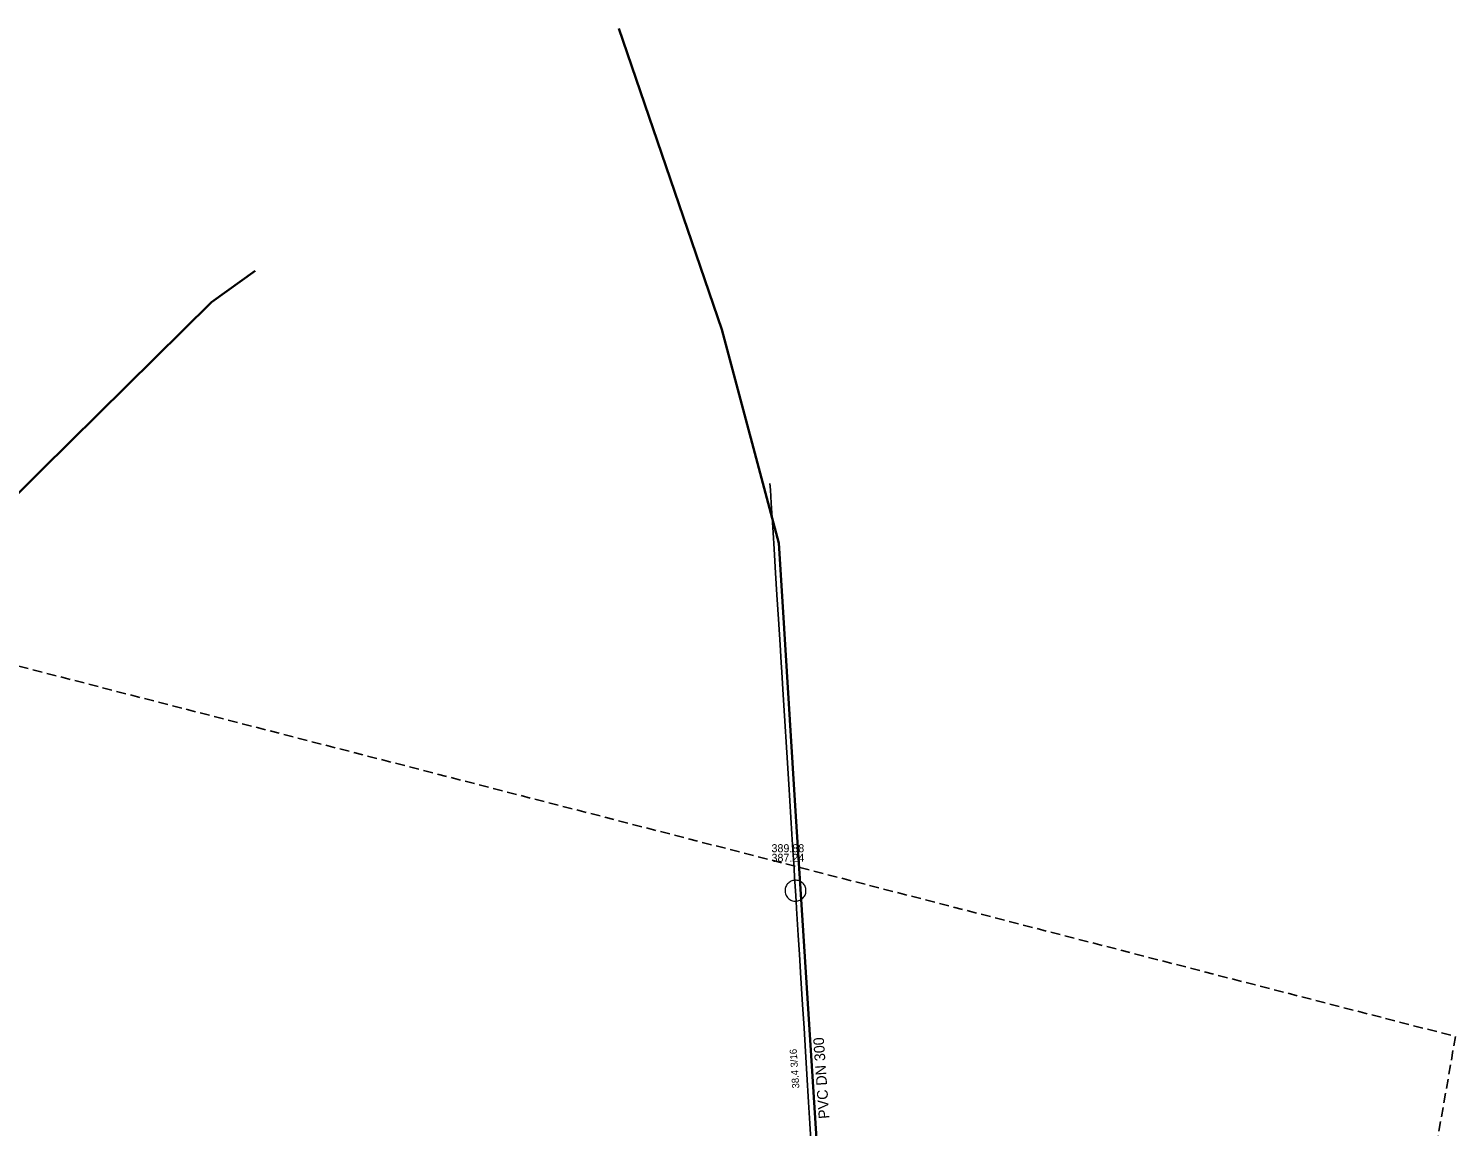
# Model space of a CAD drawing. Extents: x -772952 to -772403, y -1033777 to -1033210.
# Drawn here: x -772723 to -772562.5, y -1033333.3 to -1033209.7 of the extents above; entities that cross this region are included whole.
import ezdxf

# ---------------------------------------------------------------- set-up
doc = ezdxf.new("R2010")
doc.units = 0
doc.header["$LTSCALE"] = 0.36
doc.linetypes.add('MEDIUM_DASHED', pattern=[4.5, 3, -1.5])
for name, color, linetype, lineweight in [('16', 7, 'Continuous', 35), ('2', 7, 'Continuous', 25), ('4', 7, 'Continuous', 13), ('62', 7, 'MEDIUM_DASHED', 25)]:
    doc.layers.add(name, color=color, linetype=linetype, lineweight=lineweight)
doc.layers.add('3', color=7, linetype='Continuous')
doc.layers.add('6', color=7, linetype='Continuous')

msp = doc.modelspace()

# ---------------------------------------------------------------- linework, layer by layer
at = {"layer": '16'}
for points in [[(-772634.039, -1033339.35), (-772636.721, -1033297.19), (-772638.259, -1033272.415), (-772638.554, -1033267.657), (-772644.984, -1033243.6), (-772656.572, -1033209.741)], [(-772697.486, -1033237.004), (-772702.392, -1033240.537), (-772721.486, -1033259.44), (-772724.793, -1033262.712), (-772726.954, -1033264.853), (-772730.355, -1033268.219), (-772733.767, -1033271.598), (-772743.414, -1033281.146), (-772745.156, -1033282.871), (-772753.92, -1033291.547), (-772763.164, -1033300.699), (-772765.243, -1033302.896), (-772774.291, -1033311.64)]]:
    msp.add_lwpolyline(points, dxfattribs=at)
at = {"layer": '2'}
for points in [[(-772639.558, -1033260.939), (-772639.513, -1033261.656), (-772639.42, -1033263.132), (-772639.213, -1033266.442), (-772639.095, -1033268.322), (-772638.927, -1033270.998), (-772638.774, -1033273.446), (-772638.601, -1033276.207), (-772638.422, -1033279.065), (-772638.297, -1033281.063), (-772638.228, -1033282.163), (-772638.068, -1033284.724), (-772637.921, -1033287.063), (-772637.661, -1033291.21), (-772637.438, -1033294.77), (-772637.086, -1033300.387), (-772636.973, -1033302.2), (-772636.841, -1033304.3), (-772636.784, -1033305.207), (-772636.688, -1033306.747)], [(-772636.688, -1033306.747), (-772636.614, -1033307.94), (-772636.564, -1033308.736), (-772636.377, -1033311.752), (-772636.243, -1033313.906), (-772636.075, -1033316.603), (-772635.893, -1033319.538), (-772635.727, -1033322.199), (-772635.564, -1033324.827), (-772635.404, -1033327.402), (-772635.208, -1033330.553), (-772635.061, -1033332.92), (-772634.871, -1033335.979), (-772634.7, -1033338.723), (-772634.523, -1033341.569), (-772634.366, -1033344.097), (-772634.315, -1033344.918), (-772634.274, -1033345.566), (-772634.23, -1033346.29)]]:
    msp.add_lwpolyline(points, dxfattribs=at)
at = {"layer": '4'}
msp.add_lwpolyline([(-772635.507, -1033306.747), (-772635.514, -1033306.628), (-772635.532, -1033306.511), (-772635.561, -1033306.395), (-772635.602, -1033306.284), (-772635.654, -1033306.177), (-772635.717, -1033306.076), (-772635.789, -1033305.981), (-772635.87, -1033305.895), (-772635.961, -1033305.817), (-772636.059, -1033305.748), (-772636.162, -1033305.69), (-772636.271, -1033305.643), (-772636.385, -1033305.606), (-772636.5, -1033305.581), (-772636.619, -1033305.569), (-772636.738, -1033305.568), (-772636.857, -1033305.579), (-772636.973, -1033305.602), (-772637.087, -1033305.636), (-772637.196, -1033305.682), (-772637.301, -1033305.739), (-772637.4, -1033305.806), (-772637.49, -1033305.882), (-772637.574, -1033305.967), (-772637.647, -1033306.061), (-772637.712, -1033306.161), (-772637.766, -1033306.267), (-772637.809, -1033306.378), (-772637.841, -1033306.492), (-772637.86, -1033306.61), (-772637.868, -1033306.729), (-772637.864, -1033306.847), (-772637.848, -1033306.965), (-772637.82, -1033307.081), (-772637.781, -1033307.193), (-772637.73, -1033307.301), (-772637.669, -1033307.403), (-772637.598, -1033307.499), (-772637.517, -1033307.586), (-772637.429, -1033307.666), (-772637.333, -1033307.736), (-772637.23, -1033307.796), (-772637.122, -1033307.845), (-772637.009, -1033307.883), (-772636.892, -1033307.909), (-772636.775, -1033307.924), (-772636.656, -1033307.927), (-772636.538, -1033307.918), (-772636.419, -1033307.897), (-772636.306, -1033307.864), (-772636.196, -1033307.82), (-772636.09, -1033307.765), (-772635.99, -1033307.699), (-772635.897, -1033307.624), (-772635.814, -1033307.54), (-772635.739, -1033307.448), (-772635.673, -1033307.349), (-772635.617, -1033307.244), (-772635.573, -1033307.134), (-772635.539, -1033307.02), (-772635.517, -1033306.903), (-772635.507, -1033306.784)], close=True, dxfattribs=at)
at = {"layer": '62'}
msp.add_lwpolyline([(-772641.514, -1033776.98), (-772641.529, -1033776.987), (-772951.708, -1033584.106), (-772846.395, -1033249.938), (-772562.451, -1033323.146)], close=True, dxfattribs=at)

# ---------------------------------------------------------------- texts
at = {"layer": '3'}
for s, height, p in [('PVC DN 300', 1.2, (-772632.87, -1033332.37)), ('38.4 3/16', 0.8, (-772636.251, -1033328.971))]:
    msp.add_text(s, height=height, rotation=94, dxfattribs=at).set_placement(p)
at = {"layer": '6'}
for s, p in [('389.88', (-772639.386, -1033302.415)), ('387.24', (-772639.386, -1033303.492))]:
    msp.add_text(s, height=0.9, dxfattribs=at).set_placement(p)

doc.saveas('drawing.dxf')
